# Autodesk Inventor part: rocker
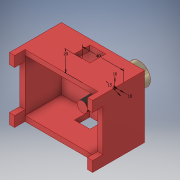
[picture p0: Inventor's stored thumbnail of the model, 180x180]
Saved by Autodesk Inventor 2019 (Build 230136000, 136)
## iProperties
Created: 2021-07
Part Number: rocker
Material: Generic
Document SubType Name: Modeling
Designer: Avinash
Density: 1 g/cm^3
Appearance: Smooth - Red
Author: Avinash
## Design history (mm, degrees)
sketch "Sketch1"
  geometry: L1 (0, 0)-(-40, 0); L2 (-40, 0)-(-40, 20); L3 (-40, 20)-(0, 20); L4 (0, 20)-(0, 0); L5 (-20, 0)-(-20, 20); C1 r 7.5 at (-10, 10); C2 r 10.567 at (-10, 10)
  constraints: 10 end point, 2 centre point, 2 midpoint, 2 parallel, 1 coincident, 1 horizontal, 1 perpendicular
  dimensions: "d0" = 20 distance of L1.end L2.end; "d1" = 40 distance of L2.end L3.end; "d2" = 15 diameter of C1; "d3" = 10 distance from line of L3 C1.centre; "d4" = 10 distance from line of L4 C1.centre
extrude "Extrusion1" new body sketch "Sketch1" distance "d5" = 5; taper "d6" = 0 deg
extrude "Extrusion2" join sketch "Sketch1" distance "d7" = 4; taper "d8" = 0 deg
extrude "Extrusion3" join sketch "Sketch1" distance "d9" = 25; taper "d10" = 0 deg
extrude "Extrusion4" join sketch "Sketch1" distance "d11" = 25; taper "d12" = 0 deg
sketch "Sketch2"
  geometry: C1 r 2.233 at (0, 0); 1 further point
  constraints: 1 centre point
extrude "Extrusion5" join sketch "Sketch2" distance "d13" = 10; taper "d14" = 0 deg
sketch "Sketch3"
  geometry: C1 r 5 at (0, 0); 1 further point
  constraints: 1 centre point
  dimensions: "d48" = 10 diameter of C1
extrude "Extrusion6" join sketch "Sketch3" distance "d15" = 20; taper "d16" = 0 deg
sketch "Sketch4"
  geometry: L1 (39.784, 20.189)-(0, 20.189); L2 (0, 20.189)-(0, 0); L3 (0, 0)-(39.784, 0); L4 (39.784, 0)-(39.784, 20.189); L5 (60.094, 40.094)-(-19.906, 40.094); L6 (-19.906, 40.094)-(-19.906, -19.906); L7 (-19.906, -19.906)-(60.094, -19.906); L8 (60.094, -19.906)-(60.094, 40.094)
  constraints: 16 end point, 2 parallel, 1 horizontal, 1 perpendicular
  dimensions: "d40" = 60 distance between parallel lines of L5 L7; "d41" = 80 distance between parallel lines of L6 L8; "d49" = 20.31068 distance between parallel lines of L4 L8
extrude "Extrusion7" join sketch "Sketch4" distance "d17" = 5; taper "d18" = 0 deg
sketch "Sketch5"
  geometry: L1 (-60.094, -19.906)-(19.906, -19.906) reference; L2 (19.906, 40.094)-(-60.094, 40.094) reference; L3 (-60.094, -19.906)-(19.906, -19.906); L4 (19.906, -19.906)-(19.906, 40.094); L5 (19.906, 40.094)-(-60.094, 40.094); L6 (-60.094, 40.094)-(-60.094, -19.906); L7 (-54.972, -15)-(15, -15); L8 (15, -15)-(15, 35.284); L9 (15, 35.284)-(-54.972, 35.284); L10 (-54.972, 35.284)-(-54.972, -15); 1 further point
  constraints: 16 end point, 2 parallel, 1 horizontal, 1 perpendicular
extrude "Extrusion8" join sketch "Sketch5" distance "d19" = 35; taper "d20" = 0 deg
sketch "Sketch9"
  geometry: L1 (-60.094, 40.094)-(19.906, 40.094) reference; L2 (-60.094, 40.094)-(-55.094, 40.094); L3 (-55.094, 40.094)-(-55.094, 30.094); L4 (-55.094, 30.094)-(-60.094, 30.094); L5 (-60.094, 30.094)-(-60.094, 40.094); L6 (-60.094, -19.906)-(-55.094, -19.906); L7 (-55.094, -19.906)-(-55.094, -9.906); L8 (-55.094, -9.906)-(-60.094, -9.906); L9 (-60.094, -9.906)-(-60.094, -19.906); L10 (19.906, 40.094)-(19.906, -19.906) reference; L11 (19.906, -19.906)-(14.906, -19.906); L12 (14.906, -19.906)-(14.906, -9.906); L13 (14.906, -9.906)-(19.906, -9.906); L14 (19.906, -9.906)-(19.906, -19.906); L15 (19.906, 40.094)-(14.906, 40.094); L16 (14.906, 40.094)-(14.906, 30.094); L17 (14.906, 30.094)-(19.906, 30.094); L18 (19.906, 30.094)-(19.906, 40.094); 1 further point
  constraints: 32 end point, 8 parallel, 4 horizontal, 4 perpendicular
  dimensions: "d23" = 5 distance of L3.end L4.end; "d24" = 10 distance of L2.end L3.end; "d25" = 5 distance of L8.end L7.end; "d26" = 5 distance of L12.end L13.end; "d27" = 10 distance of L11.end L12.end; "d28" = 5 distance of L17.end L16.end; "d29" = 10 distance of L16.end L15.end; "d42" = 10 distance of L8.end L6.start
extrude "Extrusion10" join sketch "Sketch9" distance "d30" = 10; taper "d31" = 0 deg
sketch "Sketch10"
  geometry: L1 (47.5, -40)-(32.5, -40); L2 (32.5, -20)-(32.5, -5); L3 (32.5, -5)-(47.5, -5); L4 (47.5, -5)-(47.5, -20); L5 (80, 0)-(80, -50) reference; L6 (47.5, -20)-(32.5, -20); 5 further points; 1 other entity
  constraints: 10 end point, 2 parallel, 2 perpendicular, 1 horizontal, 2 other
  dimensions: "d44" = 20 distance of the line from the sketch origin of L6; "d45" = 32.5 distance between parallel lines of L5 L4; "d46" = 15 distance of L2.start L2.end; "d47" = 15 distance of L4.end L2.start
extrude "Extrusion11" cut sketch "Sketch10" distance "d38" = 100; taper "d39" = 0 deg
body "Solid1"
